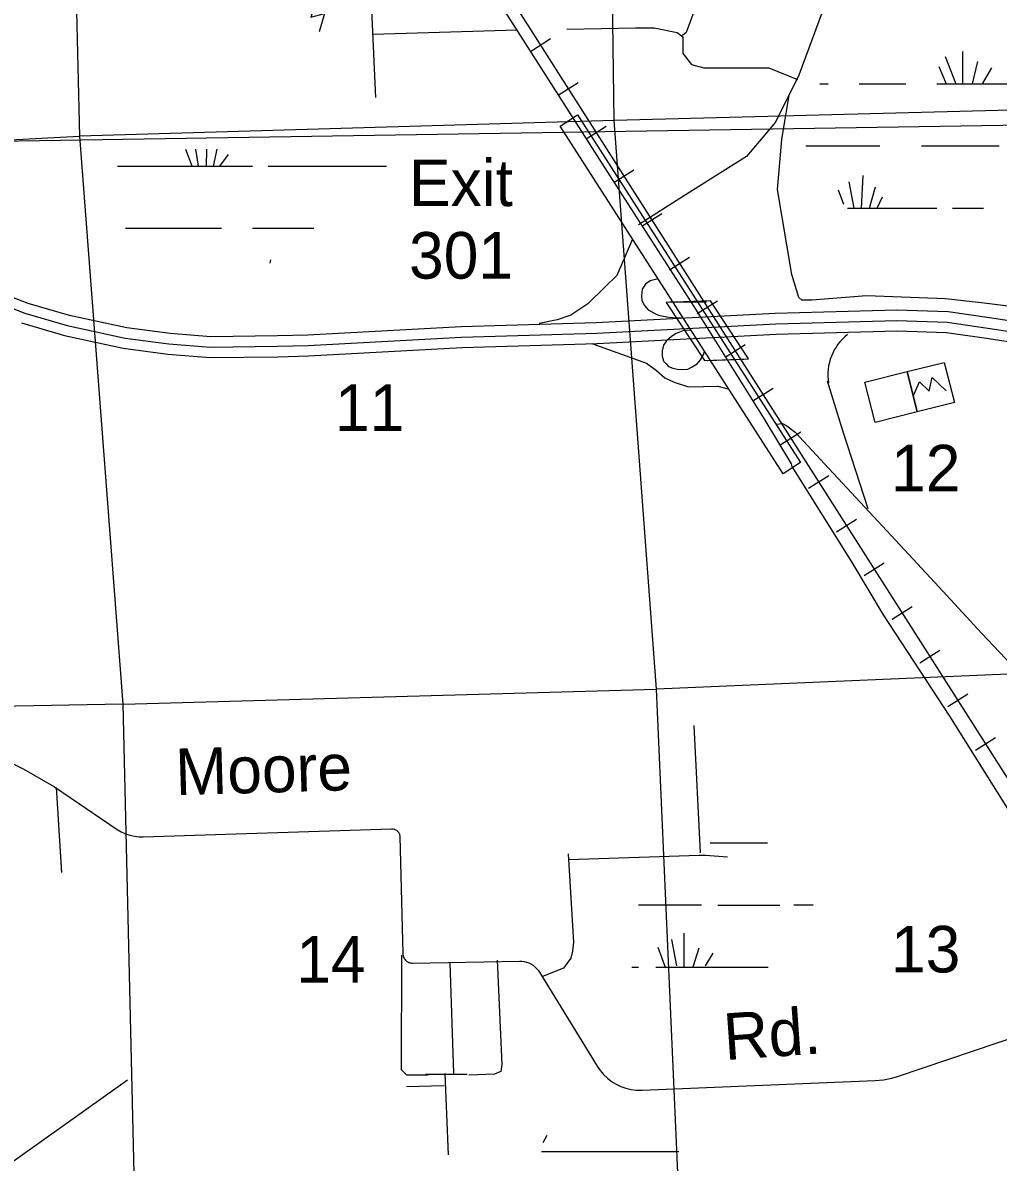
# Model space of a CAD drawing. Extents: x 2480962 to 2688785, y 277103 to 599240.
# Drawn here: x 2538319 to 2547738, y 449327 to 460329 of the extents above; entities that cross this region are included whole.
import ezdxf

# ---------------------------------------------------------------- set-up
doc = ezdxf.new("R2010")
doc.units = 0
for name, color, linetype in [('Bridges', 7, 'Continuous'), ('County Routes Highway Center Lines', 7, 'Continuous'), ('Culture', 7, 'Continuous'), ('Divided_Highway', 7, 'Continuous'), ('Interstate Divided Highway Outline and Fill', 7, 'Continuous'), ('Interstate Highway Center Lines', 7, 'Continuous'), ('Interstate Ramps', 7, 'Continuous'), ('Level 36', 7, 'Continuous'), ('Local Roads Improved', 7, 'Continuous'), ('Local Roads Paved', 7, 'Continuous'), ('Local Roads Related Text', 7, 'Continuous'), ('Railroads', 7, 'Continuous'), ('Roadshields County Roads', 7, 'Continuous'), ('Section Lines', 7, 'Continuous'), ('Section Numbers', 7, 'Continuous'), ('Swamps', 7, 'Continuous'), ('US Route Divided Highway Outline and Fill', 7, 'Continuous'), ('US Routes Highway Center Lines', 7, 'Continuous')]:
    doc.layers.add(name, color=color, linetype=linetype)

msp = doc.modelspace()

# ---------------------------------------------------------------- linework, layer by layer
at = {"layer": 'Bridges'}
for p, q in [((2544959.692, 457644.136), (2544532.718, 457629.083)), ((2544532.718, 457629.083), (2544900.629, 457069.176)), ((2544565.865, 457632.989), (2544920.958, 457635.718)), ((2545327.528, 457084.344), (2544959.692, 457644.136)), ((2544900.629, 457069.176), (2545327.528, 457084.344)), ((2544931.706, 457067.234), (2545282.652, 457079.445))]:
    msp.add_line(p, q, dxfattribs=at)
at = {"layer": 'County Routes Highway Center Lines'}
for points in [[(2546038.641, 460431.715), (2545812.314, 459822.374), (2545585.988, 459369.721), (2545307.432, 459038.936), (2544698.091, 458655.921), (2544262.847, 458377.366)], [(2545592.053, 456454.239), (2545654.709, 456459.319), (2545695.35, 456437.305), (2545776.633, 456376.342), (2546059.431, 456069.837), (2546531.889, 455561.818), (2546831.62, 455238.379), (2547163.526, 454881.072), (2547578.408, 454432.322), (2547922.168, 454071.628)]]:
    msp.add_lwpolyline(points, dxfattribs=at)
at = {"layer": 'Culture'}
for p, q in [((2546857.113, 456960.193), (2547217.03, 457050.112)), ((2547217.03, 457050.112), (2547314.031, 456661.852)), ((2546954.114, 456571.933), (2546857.113, 456960.193)), ((2547314.031, 456661.852), (2546954.114, 456571.933))]:
    msp.add_line(p, q, dxfattribs=at)
for points in [[(2540987.882, 460497.432), (2541140.499, 460506.877), (2541101.745, 460382.18), (2541230.959, 460418.045), (2541180.655, 460239.896)], [(2546916.664, 456723.386), (2546978.77, 456863.114), (2547071.475, 456771.15), (2547099.337, 456902.323), (2547234.118, 456775.429)]]:
    msp.add_lwpolyline(points, dxfattribs=at)
msp.add_lwpolyline([(2546857.113, 456960.193), (2546954.114, 456571.933), (2546547.908, 456470.449), (2546450.908, 456858.709)], close=True, dxfattribs=at)
at = {"layer": 'Divided_Highway'}
msp.add_line((2521075.087, 458914.627), (2560538.616, 459542.689), dxfattribs=at)
at = {"layer": 'Interstate Divided Highway Outline and Fill'}
for points in [[(2549126.365, 457255.598), (2547652.817, 457479.834), (2547254.782, 457536.696), (2546758.096, 457552.981), (2545585.386, 457520.852), (2543856.442, 457432.804), (2542551.697, 457392.781), (2541071.21, 457312.754), (2540777.159, 457304.807), (2540134.211, 457296.869), (2539741.195, 457328.311), (2539323.512, 457383.476), (2538770.828, 457501.909), (2538370.135, 457619.76), (2537960.897, 457777.159)], [(2538305.915, 457430.177), (2538721.59, 457307.92), (2539289.412, 457186.243), (2539720.112, 457129.358), (2540127.457, 457096.771), (2540781.095, 457104.84), (2541079.311, 457112.9), (2542560.161, 457192.946), (2543864.595, 457232.96), (2545593.212, 457320.991), (2546757.557, 457352.891), (2547237.311, 457337.161), (2547623.63, 457281.973), (2549095.412, 457058.006)]]:
    msp.add_lwpolyline(points, dxfattribs=at)
at = {"layer": 'Interstate Highway Center Lines'}
msp.add_lwpolyline([(2537921.837, 457685.041), (2538338.025, 457524.968), (2538746.209, 457404.914), (2539306.462, 457284.86), (2539730.654, 457228.835), (2540130.834, 457196.82), (2540779.127, 457204.824), (2541075.261, 457212.827), (2542555.929, 457292.864), (2543860.518, 457332.882), (2545589.299, 457420.921), (2546757.826, 457452.936), (2547246.047, 457436.929), (2547638.224, 457380.903), (2549110.889, 457156.802)], dxfattribs=at)
at = {"layer": 'Interstate Ramps'}
for p, q in [((2546240.722, 456377.74), (2546090.493, 456867.49)), ((2546483.216, 455635.518), (2546240.722, 456377.74))]:
    msp.add_line(p, q, dxfattribs=at)
for points in [[(2544207.056, 458239.663), (2544056.055, 457887.443), (2543941.469, 457780.331), (2543774.573, 457613.435), (2543610.168, 457506.322), (2543478.145, 457461.484), (2543303.776, 457426.611)], [(2544452.691, 457855.793), (2544377.637, 457837.301), (2544333.124, 457805.974), (2544298.487, 457756.685), (2544293.268, 457691.388), (2544296.289, 457646.023), (2544321.939, 457597.653), (2544357.849, 457556.613), (2544434.068, 457514.839), (2544457.673, 457507.055), (2544537.385, 457489.618), (2544619.587, 457479.654), (2544691.826, 457479.654)], [(2544764.505, 457359.354), (2544692.266, 457354.372), (2544627.501, 457329.462), (2544582.663, 457299.57), (2544535.334, 457257.223), (2544505.442, 457214.877), (2544492.987, 457160.075), (2544492.987, 457110.255), (2544505.442, 457062.926), (2544530.352, 457035.526), (2544555.262, 457010.616), (2544595.118, 456993.179), (2544639.956, 456983.215), (2544689.775, 456980.724), (2544739.595, 456985.706), (2544781.942, 457005.634), (2544829.271, 457035.526), (2544864.145, 457075.381), (2544894.036, 457130.183), (2544901.509, 457157.584)], [(2543813.532, 457230.704), (2544342.769, 457043.277), (2544437.427, 456971.039), (2544519.629, 456901.291), (2544609.305, 456858.944), (2544746.309, 456814.107), (2544893.277, 456816.598), (2545030.282, 456821.579), (2545105.011, 456801.652), (2545127.43, 456794.179)]]:
    msp.add_lwpolyline(points, dxfattribs=at)
msp.add_arc((2546585.225, 456929.689), 492.58, 127.7243612, 189.2736324, dxfattribs=at)
at = {"layer": 'Local Roads Improved'}
msp.add_line((2537882.633, 449094.21), (2539329.963, 450123.182), dxfattribs=at)
for points in [[(2542233.326, 450167.721), (2542028.119, 450167.721), (2541976.817, 450219.023), (2541978.287, 451326.098)], [(2542900.632, 451278.39), (2542943.002, 450270.325), (2542934.452, 450201.922), (2542874.599, 450176.271), (2542626.64, 450167.721)]]:
    msp.add_lwpolyline(points, dxfattribs=at)
at = {"layer": 'Local Roads Paved'}
for p, q in [((2543093.493, 460257.06), (2541697.309, 460214.428)), ((2544798.42, 453545.094), (2544858.272, 452313.849)), ((2538623.992, 452950.343), (2539230.587, 452539.159)), ((2538642.195, 452946.573), (2538693.497, 452125.743)), ((2539481.509, 452468.732), (2541880.649, 452546.065)), ((2541959.829, 452471.281), (2541987.943, 451341.331)), ((2542083.527, 451249.797), (2543114.127, 451268.791)), ((2542481.285, 450184.822), (2542447.084, 451253.611)), ((2543307.98, 451162.614), (2543864.933, 450254.608)), ((2546765.435, 450155.216), (2548627.27, 450784.884)), ((2542207.675, 450176.271), (2542609.54, 450176.271)), ((2542429.983, 449398.193), (2542395.782, 450184.822)), ((2544300.757, 450022.305), (2546548.37, 450114.899))]:
    msp.add_line(p, q, dxfattribs=at)
for points in [[(2545107.833, 463443.768), (2545171.781, 462100.874), (2545161.123, 461695.875), (2545043.886, 461258.901), (2544915.991, 460747.323), (2544809.413, 460459.56), (2544724.149, 460235.744), (2544689.949, 460204.619)], [(2541729.283, 459606.929), (2541686.652, 460523.507), (2541686.652, 460832.586), (2541697.309, 460928.507), (2541825.204, 460992.454), (2541942.441, 461035.086), (2542219.546, 461045.743), (2542592.572, 461056.401)], [(2543573.098, 460267.718), (2544233.887, 460278.376), (2544415.071, 460278.376), (2544638.886, 460235.744), (2544692.176, 460193.112), (2544692.176, 460033.244), (2544777.439, 459926.665), (2544894.676, 459894.692), (2545150.465, 459894.692), (2545427.57, 459894.692), (2545523.491, 459894.692), (2545797.967, 459782.332)], [(2549072.841, 457400.268), (2548143.623, 457552.826), (2547602.736, 457622.17), (2547228.275, 457663.777), (2546465.484, 457691.515), (2545938.465, 457649.908), (2545841.383, 457649.908), (2545813.645, 457677.646), (2545744.301, 457899.549), (2545605.611, 458717.815), (2545647.218, 459203.227), (2545720.483, 459631.239)], [(2535937.52, 453684.919), (2536517.116, 453636.297), (2536990.445, 453592.769), (2537424.794, 453537.373), (2537900.395, 453331.676), (2538330.01, 453122.61), (2538623.992, 452950.343)], [(2539230.587, 452539.159), (2539269.737, 452516.371), (2539311.054, 452497.8), (2539354.086, 452483.651), (2539398.362, 452474.076), (2539443.396, 452469.182), (2539481.509, 452468.732)], [(2541880.649, 452546.065), (2541888.679, 452545.903), (2541896.648, 452544.903), (2541904.469, 452543.075), (2541912.056, 452540.44), (2541919.326, 452537.025), (2541926.199, 452532.87), (2541932.601, 452528.019), (2541938.46, 452522.526), (2541943.713, 452516.45), (2541948.302, 452509.858), (2541952.177, 452502.823), (2541955.296, 452495.422), (2541957.623, 452487.734), (2541959.134, 452479.846), (2541959.813, 452471.843), (2541959.829, 452471.281)], [(2543584.275, 452305.299), (2543635.577, 451450.268), (2543627.027, 451364.765), (2543609.926, 451296.362), (2543541.524, 451202.309), (2543337.95, 451119.365)], [(2545123.331, 452271.098), (2544909.574, 452288.199), (2544849.721, 452288.199), (2543592.826, 452245.447)], [(2541987.943, 451341.331), (2541988.701, 451331.533), (2541990.479, 451321.868), (2541993.257, 451312.442), (2541997.006, 451303.358), (2542001.685, 451294.716), (2542007.24, 451286.609), (2542013.613, 451279.129), (2542020.732, 451272.355), (2542028.52, 451266.362), (2542036.893, 451261.217), (2542045.757, 451256.974), (2542055.016, 451253.683), (2542064.568, 451251.376), (2542074.31, 451250.081), (2542083.527, 451249.797)], [(2543114.127, 451268.791), (2543137.414, 451268.001), (2543160.491, 451264.78), (2543183.105, 451259.165), (2543205.009, 451251.217), (2543225.961, 451241.023), (2543245.733, 451228.694), (2543264.108, 451214.367), (2543280.884, 451198.196), (2543295.879, 451180.361), (2543307.98, 451162.614)], [(2543864.933, 450254.608), (2543893.867, 450212.547), (2543927.039, 450173.74), (2543964.086, 450138.614), (2544004.602, 450107.552), (2544048.142, 450080.897), (2544094.23, 450058.937), (2544142.361, 450041.917), (2544192.007, 450030.02), (2544242.626, 450023.378), (2544293.661, 450022.064), (2544300.757, 450022.305)], [(2546548.37, 450114.899), (2546629.391, 450122.499), (2546709.172, 450138.527), (2546765.435, 450155.216)]]:
    msp.add_lwpolyline(points, dxfattribs=at)
at = {"layer": 'Railroads'}
for p, q in [((2543414.223, 460172.06), (2543220.24, 460048.486)), ((2543682.863, 459750.357), (2543488.88, 459626.783)), ((2543951.502, 459328.655), (2543757.519, 459205.081)), ((2544220.141, 458906.952), (2544026.158, 458783.378)), ((2544488.781, 458485.25), (2544294.798, 458361.676)), ((2544757.42, 458063.548), (2544563.437, 457939.974)), ((2545026.059, 457641.845), (2544832.076, 457518.271)), ((2545294.699, 457220.143), (2545100.716, 457096.569)), ((2545563.338, 456798.44), (2545369.355, 456674.866)), ((2545831.977, 456376.738), (2545637.994, 456253.164)), ((2546100.617, 455955.036), (2545906.633, 455831.462)), ((2546369.256, 455533.333), (2546175.273, 455409.759)), ((2546637.895, 455111.631), (2546443.912, 454988.057)), ((2546906.535, 454689.928), (2546712.551, 454566.354)), ((2547175.174, 454268.226), (2546981.191, 454144.652)), ((2547443.813, 453846.524), (2547249.83, 453722.95)), ((2547712.452, 453424.821), (2547518.469, 453301.247))]:
    msp.add_line(p, q, dxfattribs=at)
for points in [[(2535189.55, 474029.408), (2536089.7, 471644.944), (2536291.253, 471185.4), (2536531.488, 470762.342), (2552586.883, 445559.036), (2552586.884, 445559.036), (2553075.384, 444874.143), (2553427.841, 444460.531), (2556691.947, 440882.519), (2556841.764, 440734.641), (2557006.218, 440603.234), (2557183.506, 440489.737), (2557371.687, 440395.394), (2557568.699, 440321.239), (2557735.519, 440276.028), (2568072.12, 437946.462), (2568887.934, 437807.005), (2569361.53, 437765.755), (2570495.789, 437701.245), (2571983.523, 437694.622), (2573132.142, 437796.523), (2616563.163, 443432.973)], [(2536531.488, 470762.342), (2552586.883, 445559.036), (2552586.884, 445559.036), (2553075.384, 444874.143), (2553427.841, 444460.531), (2556691.947, 440882.519), (2556841.764, 440734.641), (2557006.218, 440603.234), (2557183.506, 440489.737), (2557371.687, 440395.394), (2557568.699, 440321.239), (2557735.519, 440276.028), (2568072.12, 437946.462), (2568887.934, 437807.005), (2569361.53, 437765.755), (2570495.789, 437701.245), (2571983.523, 437694.622), (2573132.142, 437796.523), (2616563.163, 443432.973)]]:
    msp.add_lwpolyline(points, dxfattribs=at)
at = {"layer": 'Section Lines'}
for p, q in [((2544027.913, 459386.313), (2543964.503, 464723.862)), ((2538737.603, 464487.596), (2538867.356, 459234.171)), ((2549306.726, 459520.847), (2544027.916, 459386.319)), ((2544027.913, 459386.313), (2538867.356, 459234.171)), ((2544439.291, 453895.549), (2544027.916, 459386.319)), ((2533555.229, 458950.613), (2538867.356, 459234.171)), ((2538867.356, 459234.171), (2539284.281, 453748.786)), ((2549484.991, 454107.216), (2544439.291, 453895.549)), ((2539288.402, 453748.9), (2544439.291, 453895.549)), ((2544672.431, 448617.705), (2544439.291, 453895.549)), ((2539288.402, 453748.9), (2534829.13, 453671.512)), ((2539284.282, 453748.783), (2539408.867, 448484.921))]:
    msp.add_line(p, q, dxfattribs=at)
at = {"layer": 'Swamps'}
for p, q in [((2547224.971, 460001.865), (2547327.992, 459739.192)), ((2547394.122, 460050.196), (2547394.126, 459739.193)), ((2547164.561, 459905.206), (2547235.374, 459739.19)), ((2547539.109, 459953.541), (2547485.501, 459739.094)), ((2547672.015, 459893.132), (2547582.297, 459739.325)), ((2546395.471, 459739.176), (2546845.469, 459739.184)), ((2547145.468, 459739.189), (2548495.463, 459739.211)), ((2546995.476, 459139.185), (2547745.473, 459139.197)), ((2540222.847, 458943.668), (2540306.625, 459057.371)), ((2539787.39, 458944.158), (2540537.387, 458944.171)), ((2546345.994, 458539.248), (2546299.74, 458793.633)), ((2546416.994, 458539.199), (2546434.231, 458855.278)), ((2546493.68, 458539.378), (2546551.912, 458743.201)), ((2546570.276, 458539.301), (2546619.159, 458647.936)), ((2547295.482, 458539.181), (2547595.481, 458539.186)), ((2539787.397, 458344.149), (2540237.395, 458344.157)), ((2539284.282, 453748.783), (2539288.402, 453748.9)), ((2544263.671, 451811.773), (2544872.897, 451811.784)), ((2545028.752, 451809.169), (2545628.75, 451809.179)), ((2544703.236, 451537.998), (2544703.24, 451211.773)), ((2544449.511, 451405.087), (2544522.007, 451211.769)), ((2544582.415, 451477.584), (2544630.746, 451223.853)), ((2544848.225, 451393.012), (2544787.816, 451211.774)), ((2544981.13, 451344.684), (2544908.638, 451223.858)), ((2544431.924, 451211.768), (2545031.922, 451211.778)), ((2542387.409, 450065.762), (2542023.445, 450055.934)), ((2544203.656, 449429.65), (2544653.654, 449429.658))]:
    msp.add_line(p, q, dxfattribs=at)
for points in [[(2546014.789, 459739.17), (2546095.472, 459739.171)], [(2539953.069, 458945.148), (2539891.661, 459105.754)], [(2540015.391, 458944.226), (2539990.094, 459106.843)], [(2540093.553, 458944.183), (2540096.643, 459108.023)], [(2540160.652, 458943.975), (2540195.055, 459109.113)], [(2545880.294, 459139.166), (2546595.478, 459139.178)], [(2539233.826, 458944.149), (2539787.39, 458944.158)], [(2540687.387, 458944.173), (2541831.956, 458944.192)], [(2546247.781, 458573.829), (2546195.448, 458711.203)], [(2546282.351, 458539.165), (2547145.482, 458539.179)], [(2539309.284, 458344.142), (2539787.397, 458344.149)], [(2540537.394, 458344.162), (2541128.562, 458344.172)], [(2540711.247, 458038.968), (2540705.099, 458008.22)], [(2544955.055, 452411.794), (2545031.909, 452411.796)], [(2545031.909, 452411.796), (2545509.58, 452411.804)], [(2545763.666, 451811.8), (2545950.008, 451811.803)], [(2544198.806, 451211.764), (2544262.781, 451211.765)], [(2545031.922, 451211.778), (2545514.949, 451211.787)], [(2543380.208, 449583.573), (2543340.691, 449515.825)], [(2543327.759, 449429.634), (2544203.656, 449429.65)]]:
    msp.add_lwpolyline(points, dxfattribs=at)
at = {"layer": 'US Route Divided Highway Outline and Fill'}
for p, q in [((2543507.026, 459331.7), (2543675.392, 459439.648)), ((2543675.392, 459439.648), (2545828.457, 456081.544)), ((2545660.171, 455973.472), (2543507.026, 459331.7)), ((2545828.457, 456081.544), (2545660.171, 455973.472))]:
    msp.add_line(p, q, dxfattribs=at)
at = {"layer": 'US Routes Highway Center Lines'}
for points in [[(2537341.586, 469291.003), (2538342.082, 467731.72), (2538693.32, 467178.254), (2539033.914, 466646.075), (2539108.42, 466518.352), (2540034.411, 465086.791), (2540577.233, 464208.696), (2540917.827, 463671.195), (2541013.62, 463538.151), (2541902.358, 462122.555), (2542407.928, 461324.287), (2542823.027, 460680.35), (2542950.75, 460472.801), (2543663.87, 459360.547), (2543988.499, 458849.655)], [(2543988.499, 458849.655), (2544797.411, 457588.392), (2545473.278, 456508.069), (2545739.367, 456071.682), (2545744.689, 456045.073)], [(2545744.689, 456045.073), (2546319.442, 455124.404), (2546628.106, 454613.512), (2547266.72, 453634.303), (2547825.508, 452745.565), (2548416.227, 451803.608), (2548522.662, 451659.92), (2549145.312, 450659.424), (2549682.812, 449802.616), (2550188.382, 449004.348), (2550252.243, 448892.59), (2550736.526, 448147.54), (2551274.027, 447306.697), (2551721.057, 446588.256), (2552051.008, 446082.686), (2552109.547, 446002.859), (2552407.568, 445523.898), (2552625.761, 445204.591), (2552945.068, 444725.63), (2553349.524, 444172.164), (2553663.51, 443778.352), (2553870.308, 443507.571)]]:
    msp.add_lwpolyline(points, dxfattribs=at)

# ---------------------------------------------------------------- texts
at = {"layer": 'Level 36'}
for s, p in [('13', (2546702.598, 451159.314)), ('14', (2540959.201, 451061.247))]:
    msp.add_text(s, height=450, rotation=359.9795056, dxfattribs=at).set_placement(p)
at = {"layer": 'Local Roads Related Text'}
for s, rotation, p in [('Moore', 1.6939139, (2539797.978, 452869.908)), ('Rd.', 4.0287139, (2545101.06, 450312.5))]:
    msp.add_text(s, height=450, rotation=rotation, dxfattribs=at).set_placement(p)
at = {"layer": 'Roadshields County Roads'}
for s, p in [('Exit', (2542048.476, 458558.122)), ('301', (2542048.489, 457858.122))]:
    msp.add_text(s, height=450, rotation=0.0009944, dxfattribs=at).set_placement(p)
at = {"layer": 'Section Numbers'}
for s, p in [('11', (2541333.156, 456387.514)), ('12', (2546703.163, 455803.925))]:
    msp.add_text(s, height=450, rotation=359.9794583, dxfattribs=at).set_placement(p)

doc.saveas('drawing.dxf')
